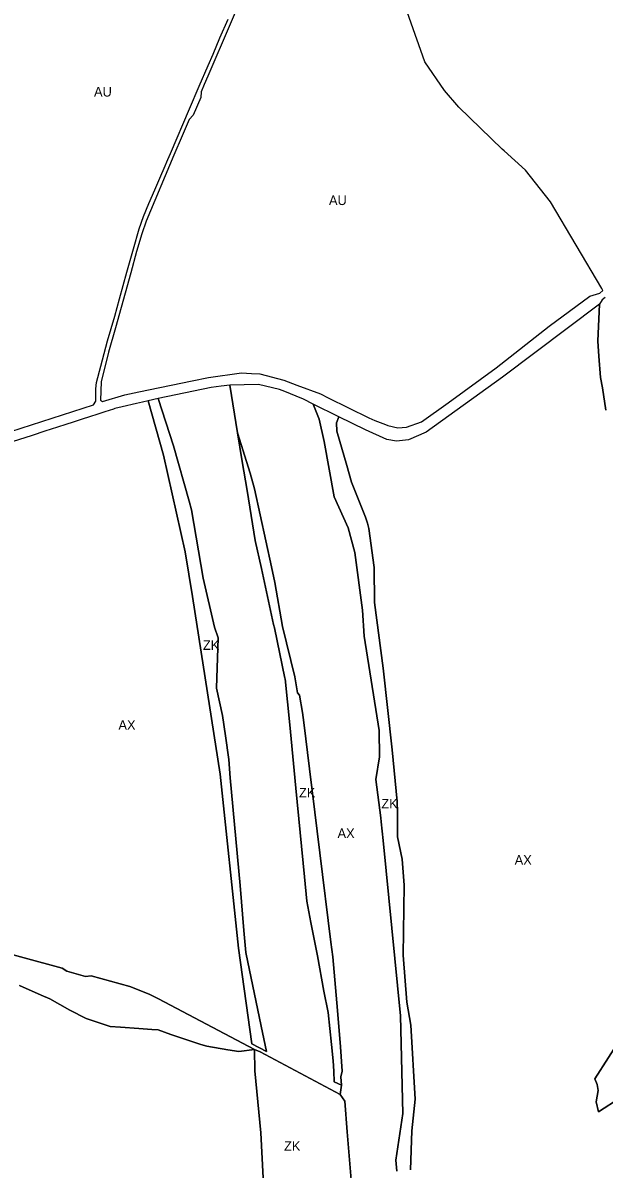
# Model space of a CAD drawing. Extents: x -521939 to -516426, y -1197857 to -1189551.
# Drawn here: x -518681 to -518075, y -1192149 to -1190954 of the extents above; entities that cross this region are included whole.
import ezdxf

# ---------------------------------------------------------------- set-up
doc = ezdxf.new("R2010")
doc.units = 0
for name, color, linetype in [('90710013', 7, 'Continuous'), ('90750013', 7, 'Continuous'), ('90760013', 7, 'Continuous')]:
    doc.layers.add(name, color=color, linetype=linetype)

msp = doc.modelspace()

# ---------------------------------------------------------------- linework, layer by layer
at = {"layer": '90710013'}
for points in [[(-518073.93, -1191240.12), (-518077.16, -1191242.55), (-518079.95, -1191247.19), (-518081.72, -1191285.53), (-518080.59, -1191301.43), (-518078.94, -1191323.44), (-518076.64, -1191334.54), (-518073.11, -1191357.72)], [(-518539.79, -1191345.38), (-518550.53, -1191347.83), (-518534.55, -1191404.6), (-518511.67, -1191505.47), (-518504.02, -1191551.95), (-518475.27, -1191737.43), (-518456.08, -1191919), (-518442.18, -1192018.62), (-518426.98, -1192026.71), (-518432.53, -1192000.31), (-518448.71, -1191923.59), (-518450.7, -1191900.44), (-518454.59, -1191853.4), (-518464.87, -1191741.35), (-518466.4, -1191722.26), (-518469.66, -1191697.37), (-518473.02, -1191676.18), (-518479.16, -1191647.79), (-518477.36, -1191595.24), (-518481.26, -1191583.91), (-518492.98, -1191533.04), (-518505.21, -1191461.73), (-518507.78, -1191452.68), (-518523.95, -1191394.84), (-518539.79, -1191345.38)], [(-518351.67, -1191364.52), (-518378.34, -1191351.41), (-518372.26, -1191367.06), (-518366.94, -1191390.2), (-518356.39, -1191448.17), (-518342, -1191480.43), (-518334.85, -1191506.3), (-518326.95, -1191566.18), (-518325.04, -1191593.59), (-518309.54, -1191691.73), (-518309.12, -1191719.22), (-518313.13, -1191742.82), (-518307.95, -1191783.04), (-518307.55, -1191787.05), (-518305.35, -1191806.74), (-518287.42, -1191989.44), (-518284.75, -1192091.34), (-518292.25, -1192140.07), (-518291.06, -1192151.72)], [(-518276.97, -1192150.12), (-518275.47, -1192109.47), (-518272.1, -1192076.35), (-518276.42, -1191999.25), (-518280.69, -1191975.27), (-518284.63, -1191926.19), (-518283.49, -1191853.16), (-518285.42, -1191826.12), (-518290.26, -1191802.68), (-518290.41, -1191787.66), (-518290.52, -1191777.09), (-518290.64, -1191765.8), (-518295.95, -1191711.97), (-518305.44, -1191626.9), (-518314.3, -1191558.4), (-518314.72, -1191521.75), (-518320.14, -1191481.08), (-518321.64, -1191475.46), (-518323.66, -1191469.47), (-518338.5, -1191432.91), (-518343.3, -1191415.51), (-518353.74, -1191379.46), (-518354, -1191370.72), (-518351.67, -1191364.52)], [(-518348.78, -1192061.86), (-518349.5, -1192053.03), (-518348.09, -1192047.23), (-518350.01, -1192021.8), (-518353.13, -1191983.99), (-518357.94, -1191927.95), (-518359.88, -1191912.56), (-518362.56, -1191890.14), (-518368.51, -1191841.95), (-518382.15, -1191731.8), (-518388.12, -1191683.62), (-518389.54, -1191673.05), (-518392.61, -1191655.06), (-518394.56, -1191652.47), (-518397.54, -1191635.81), (-518410.47, -1191583.23), (-518418.21, -1191537.31), (-518421.64, -1191520.99), (-518439.4, -1191439.86), (-518443.9, -1191423.5), (-518457.15, -1191381.15), (-518452.22, -1191411.25), (-518447.28, -1191441.34), (-518438.67, -1191493.81), (-518432.33, -1191522.8), (-518419.55, -1191581.22), (-518418.81, -1191584.73), (-518407.73, -1191637.31), (-518407.6, -1191637.9), (-518402.84, -1191686.1), (-518398.14, -1191733.65), (-518396.33, -1191751.94), (-518387.48, -1191844.47), (-518385.07, -1191869.74), (-518380.62, -1191892.25), (-518376.2, -1191914.59), (-518373.8, -1191926.76), (-518367.31, -1191963.64), (-518362.87, -1191986.17), (-518359.25, -1192019.39), (-518357.41, -1192036.36), (-518356.87, -1192047.41), (-518356.33, -1192058.47), (-518348.78, -1192061.86)], [(-518684.53, -1191957.75), (-518662.07, -1191967.96), (-518652.92, -1191971.91), (-518632.1, -1191983.6), (-518614.88, -1191992.25), (-518589.96, -1192000.69), (-518579.38, -1192001.45), (-518560.26, -1192002.77), (-518546.52, -1192003.71), (-518540.04, -1192004.16), (-518526.74, -1192009.01), (-518495.32, -1192019.58), (-518489.35, -1192021.32), (-518467.2, -1192024.87), (-518455.87, -1192026.74), (-518439.37, -1192024.6), (-518539.66, -1191971.83), (-518549.43, -1191967.03), (-518569.67, -1191959.07), (-518609.83, -1191947.89), (-518615.81, -1191948.34), (-518635.28, -1191943.07), (-518640.22, -1191939.66), (-518719.73, -1191918.12)], [(-518056.12, -1192010.8), (-518084.56, -1192055.3), (-518082.39, -1192061.11), (-518081.28, -1192067.38), (-518083.39, -1192079.13), (-518080.71, -1192089.58), (-518058.25, -1192075.03)], [(-518338.7, -1192160.53), (-518343.05, -1192110.36), (-518345.44, -1192078.61), (-518350.12, -1192071.56), (-518433.62, -1192027.04), (-518439.37, -1192024.6), (-518439.2, -1192046.97), (-518433.03, -1192111.71), (-518430.38, -1192158.5)]]:
    msp.add_lwpolyline(points, dxfattribs=at)
at = {"layer": '90750013'}
for points in [[(-518418.31, -1190846.1), (-518488.26, -1191009.23), (-518491.95, -1191017.84), (-518495.2, -1191025.44), (-518495.59, -1191031.42), (-518503.54, -1191049.96), (-518507.61, -1191054.38), (-518514.91, -1191071.43), (-518523.64, -1191091.67), (-518552.56, -1191160.42), (-518557.09, -1191173.61), (-518562.4, -1191192.05), (-518568.6, -1191214.46), (-518584.58, -1191271.86), (-518591.57, -1191297.08), (-518599.26, -1191327.96), (-518600.13, -1191347.15), (-518597.86, -1191348.78), (-518574.7, -1191341.77), (-518560.07, -1191338.6), (-518504.38, -1191327.08), (-518487.56, -1191323.54), (-518453.2, -1191318.84), (-518442.61, -1191319.4), (-518434.03, -1191319.91), (-518409.06, -1191326.28), (-518395.42, -1191331.64), (-518370.69, -1191340.74), (-518362.77, -1191344.93), (-518320.35, -1191365.76), (-518314.03, -1191368.34), (-518302.98, -1191372.66), (-518300.36, -1191373.65), (-518290.09, -1191375.94), (-518281.19, -1191375.52), (-518265.33, -1191369.69), (-518237.69, -1191349.9), (-518187.56, -1191313.35), (-518132.45, -1191270.05), (-518089.73, -1191238.72), (-518079.58, -1191235.56), (-518076.18, -1191232.9)], [(-518076.18, -1191232.9), (-518077.55, -1191230.58), (-518130.99, -1191140.28), (-518157.01, -1191107.19), (-518179.38, -1191087.17), (-518181.2, -1191085.54), (-518226.41, -1191041.52), (-518241.31, -1191024.36), (-518262.08, -1190994.23), (-518292.5, -1190907.44)], [(-518747.87, -1191397.44), (-518607.36, -1191351.98), (-518604.8, -1191348.36), (-518604.95, -1191341.26), (-518604.91, -1191335.5), (-518604.14, -1191328.7), (-518599.74, -1191311.94), (-518592.95, -1191285.51), (-518585.29, -1191259.6), (-518580.36, -1191241.38), (-518572.51, -1191213.54), (-518565.8, -1191189.41), (-518559.64, -1191168.45), (-518555.14, -1191155.79), (-518549.53, -1191142.04), (-518543.4, -1191127.65), (-518537.15, -1191113.29), (-518533.75, -1191105.26), (-518529.88, -1191096.22), (-518527.2, -1191089.94), (-518507.28, -1191043.48), (-518497.07, -1191019.7), (-518487.87, -1190998.24), (-518482.71, -1190986.39), (-518475.51, -1190969.38), (-518467.11, -1190949.79)]]:
    msp.add_lwpolyline(points, dxfattribs=at)
at = {"layer": '90760013'}
for points in [[(-518073.11, -1191357.72), (-518076.64, -1191334.54), (-518078.94, -1191323.44), (-518080.59, -1191301.43), (-518081.72, -1191285.53), (-518079.95, -1191247.19), (-518180.89, -1191323.09), (-518260.37, -1191380.66), (-518279.05, -1191388.52), (-518291.56, -1191389.89), (-518301.6, -1191388.22), (-518323.66, -1191378.34), (-518351.67, -1191364.52)], [(-518348.78, -1192061.86), (-518356.33, -1192058.47), (-518356.87, -1192047.41), (-518357.41, -1192036.36), (-518359.25, -1192019.39), (-518362.87, -1191986.17), (-518367.31, -1191963.64), (-518373.8, -1191926.76), (-518376.2, -1191914.59), (-518380.62, -1191892.25), (-518385.07, -1191869.74), (-518387.48, -1191844.47), (-518396.33, -1191751.94), (-518398.14, -1191733.65), (-518402.84, -1191686.1), (-518407.6, -1191637.9), (-518407.73, -1191637.31), (-518418.81, -1191584.73), (-518419.55, -1191581.22), (-518432.33, -1191522.8), (-518438.67, -1191493.81), (-518447.28, -1191441.34), (-518452.22, -1191411.25), (-518457.15, -1191381.15), (-518465.41, -1191331.65), (-518474.1, -1191332.51), (-518484.81, -1191334.03), (-518539.79, -1191345.38), (-518523.95, -1191394.84), (-518507.78, -1191452.68), (-518505.21, -1191461.73), (-518492.98, -1191533.04), (-518481.26, -1191583.91), (-518477.36, -1191595.24), (-518479.16, -1191647.79), (-518473.02, -1191676.18), (-518469.66, -1191697.37), (-518466.4, -1191722.26), (-518464.87, -1191741.35), (-518454.59, -1191853.4), (-518450.7, -1191900.44), (-518448.71, -1191923.59), (-518432.53, -1192000.31), (-518426.98, -1192026.71), (-518442.18, -1192018.62), (-518456.08, -1191919), (-518475.27, -1191737.43), (-518504.02, -1191551.95), (-518511.67, -1191505.47), (-518534.55, -1191404.6), (-518550.53, -1191347.83), (-518556.44, -1191349.16), (-518562.41, -1191350.57), (-518577.45, -1191354.24), (-518585.03, -1191356.06), (-518586.36, -1191356.49), (-518595.54, -1191359.34), (-518602.82, -1191361.7), (-518611.69, -1191364.61), (-518619.05, -1191366.96), (-518628.73, -1191370.13), (-518636.18, -1191372.55), (-518644.76, -1191375.36), (-518658, -1191379.69), (-518671.16, -1191383.98), (-518692.08, -1191390.79)], [(-518291.06, -1192151.72), (-518292.25, -1192140.07), (-518284.75, -1192091.34), (-518287.42, -1191989.44), (-518305.35, -1191806.74), (-518307.55, -1191787.05), (-518307.95, -1191783.04), (-518313.13, -1191742.82), (-518309.12, -1191719.22), (-518309.54, -1191691.73), (-518325.04, -1191593.59), (-518326.95, -1191566.18), (-518334.85, -1191506.3), (-518342, -1191480.43), (-518356.39, -1191448.17), (-518366.94, -1191390.2), (-518372.26, -1191367.06), (-518378.34, -1191351.41), (-518388.42, -1191346.21), (-518395.95, -1191343.18), (-518407.75, -1191338.3), (-518413.58, -1191336.14), (-518428, -1191332.68), (-518435.2, -1191331), (-518465.41, -1191331.65), (-518457.15, -1191381.15), (-518443.9, -1191423.5), (-518439.4, -1191439.86), (-518421.64, -1191520.99), (-518418.21, -1191537.31), (-518410.47, -1191583.23), (-518397.54, -1191635.81), (-518394.56, -1191652.47), (-518392.61, -1191655.06), (-518389.54, -1191673.05), (-518388.12, -1191683.62), (-518382.15, -1191731.8), (-518368.51, -1191841.95), (-518362.56, -1191890.14), (-518359.88, -1191912.56), (-518357.94, -1191927.95), (-518353.13, -1191983.99), (-518350.01, -1192021.8), (-518348.09, -1192047.23), (-518349.5, -1192053.03), (-518348.78, -1192061.86), (-518350.12, -1192071.56), (-518345.44, -1192078.61), (-518343.05, -1192110.36), (-518338.7, -1192160.53)], [(-518351.67, -1191364.52), (-518354, -1191370.72), (-518353.74, -1191379.46), (-518343.3, -1191415.51), (-518338.5, -1191432.91), (-518323.66, -1191469.47), (-518321.64, -1191475.46), (-518320.14, -1191481.08), (-518314.72, -1191521.75), (-518314.3, -1191558.4), (-518305.44, -1191626.9), (-518295.95, -1191711.97), (-518290.64, -1191765.8), (-518290.52, -1191777.09), (-518290.41, -1191787.66), (-518290.26, -1191802.68), (-518285.42, -1191826.12), (-518283.49, -1191853.16), (-518284.63, -1191926.19), (-518280.69, -1191975.27), (-518276.42, -1191999.25), (-518272.1, -1192076.35), (-518275.47, -1192109.47), (-518276.97, -1192150.12)], [(-518719.73, -1191918.12), (-518640.22, -1191939.66), (-518635.28, -1191943.07), (-518615.81, -1191948.34), (-518609.83, -1191947.89), (-518569.67, -1191959.07), (-518549.43, -1191967.03), (-518539.66, -1191971.83), (-518439.37, -1192024.6), (-518433.62, -1192027.04), (-518350.12, -1192071.56), (-518348.78, -1192061.86)], [(-518430.38, -1192158.5), (-518433.03, -1192111.71), (-518439.2, -1192046.97), (-518439.37, -1192024.6), (-518455.87, -1192026.74), (-518467.2, -1192024.87), (-518489.35, -1192021.32), (-518495.32, -1192019.58), (-518526.74, -1192009.01), (-518540.04, -1192004.16), (-518546.52, -1192003.71), (-518560.26, -1192002.77), (-518579.38, -1192001.45), (-518589.96, -1192000.69), (-518614.88, -1191992.25), (-518632.1, -1191983.6), (-518652.92, -1191971.91), (-518662.07, -1191967.96), (-518684.53, -1191957.75)], [(-518058.25, -1192075.03), (-518080.71, -1192089.58), (-518083.39, -1192079.13), (-518081.28, -1192067.38), (-518082.39, -1192061.11), (-518084.56, -1192055.3), (-518056.12, -1192010.8)]]:
    msp.add_lwpolyline(points, dxfattribs=at)

# ---------------------------------------------------------------- texts
at = {"layer": '90710013'}
for rotation, p in [(0, (-518493.32, -1191607.76)), (0, (-518393.1, -1191761.7)), (0, (-518307.26, -1191773.15)), (360, (-518408.73, -1192130.33))]:
    msp.add_text('ZK', height=10, rotation=rotation, dxfattribs=at).set_placement(p)
at = {"layer": '90750013'}
for p in [(-518606.84, -1191030.49), (-518361.88, -1191143.68)]:
    msp.add_text('AU', height=10, rotation=360, dxfattribs=at).set_placement(p)
at = {"layer": '90760013'}
for p in [(-518581.38, -1191691.12), (-518352.96, -1191804.05)]:
    msp.add_text('AX', height=10, rotation=0, dxfattribs=at).set_placement(p)
msp.add_text('AX', height=10, dxfattribs=at).set_placement((-518168.27, -1191831.86))

doc.saveas('drawing.dxf')
